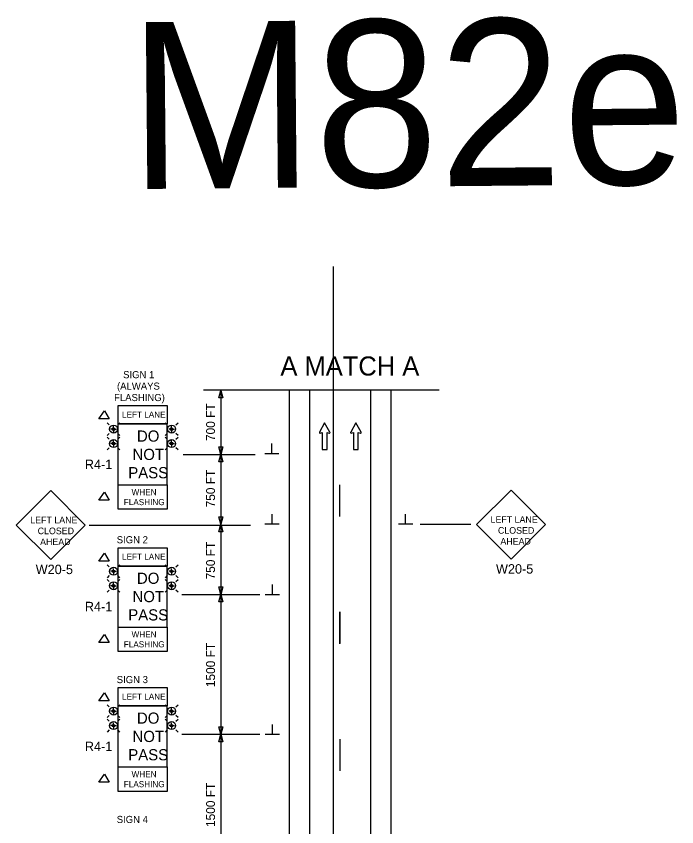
# Model space of a CAD drawing. Extents: x 15273 to 18137, y 1908 to 6555.
# Drawn here: x 16362 to 16881, y 2796 to 3433 of the extents above; entities that cross this region are included whole.
import ezdxf

# ---------------------------------------------------------------- set-up
doc = ezdxf.new("R2010")
doc.units = 0
for name, color, linetype in [('ALI_LEGAL_EX', 7, 'Continuous'), ('MT_SCRATCH_LEVEL_E', 7, 'Continuous'), ('PAVT_EDGE_EX', 7, 'Continuous'), ('TRAFFIC_SIGNS_PR', 7, 'Continuous'), ('TYPICAL_TEXT_DIMEN_PR', 7, 'Continuous')]:
    doc.layers.add(name, color=color, linetype=linetype)

msp = doc.modelspace()

# ---------------------------------------------------------------- linework, layer by layer
at = {"layer": 'ALI_LEGAL_EX'}
msp.add_line((16610.98, 3236.46), (16610.98, 2407.28), dxfattribs=at)
for points in [[(16616.07, 3064.67), (16616.07, 3039.67)], [(16616.07, 2964.67), (16616.07, 2939.67)], [(16616.35, 2964.74), (16616.35, 2939.74)], [(16616.35, 2864.74), (16616.35, 2839.74)]]:
    msp.add_lwpolyline(points, dxfattribs=at)
at = {"layer": 'MT_SCRATCH_LEVEL_E'}
for p, q in [((16604.32, 3113.3), (16600.21, 3106.06)), ((16608.47, 3106.06), (16604.32, 3113.3)), ((16628.88, 3113.3), (16624.77, 3106.06)), ((16633.03, 3106.06), (16628.88, 3113.3)), ((16600.69, 3105.38), (16602.47, 3105.69)), ((16602.47, 3105.69), (16602.47, 3092.43)), ((16606.21, 3092.43), (16606.21, 3105.69)), ((16606.21, 3105.69), (16607.99, 3105.38)), ((16625.25, 3105.38), (16627.03, 3105.69)), ((16627.03, 3105.69), (16627.03, 3092.43)), ((16630.77, 3092.43), (16630.77, 3105.69)), ((16630.77, 3105.69), (16632.55, 3105.38)), ((16602.47, 3092.43), (16606.21, 3092.43)), ((16627.03, 3092.43), (16630.77, 3092.43))]:
    msp.add_line(p, q, dxfattribs=at)
for centre, start, end in [((16600.62, 3105.84), 150.42484, 279.96381), ((16608.06, 3105.84), 260.03619, 29.77312), ((16625.17, 3105.84), 150.42484, 279.96381), ((16632.62, 3105.84), 260.03619, 29.77312)]:
    msp.add_arc(centre, 0.463, start, end, dxfattribs=at)
at = {"layer": 'PAVT_EDGE_EX'}
for p, q in [((16576.35, 3138.78), (16576.35, 2305.55)), ((16592.35, 3138.78), (16592.35, 2305.55)), ((16640.35, 3138.78), (16640.35, 2305.55)), ((16656.35, 3138.78), (16656.35, 2305.55))]:
    msp.add_line(p, q, dxfattribs=at)
at = {"layer": 'TRAFFIC_SIGNS_PR'}
for p, q in [((16434.9, 3111.91), (16433.27, 3113.53)), ((16441.74, 3111.91), (16443.37, 3113.53)), ((16442.06, 3064.61), (16442.06, 3112.61)), ((16442.06, 3112.61), (16480.46, 3112.61)), ((16480.54, 3111.92), (16478.91, 3113.55)), ((16480.46, 3064.61), (16480.46, 3112.61)), ((16487.39, 3111.92), (16489.02, 3113.55)), ((16434.9, 3105.06), (16433.27, 3103.43)), ((16438.32, 3108.48), (16436.02, 3108.48)), ((16438.32, 3108.48), (16438.32, 3110.78)), ((16438.32, 3108.48), (16438.32, 3105.33)), ((16438.32, 3108.48), (16440.62, 3108.48)), ((16443.37, 3103.43), (16441.74, 3105.06)), ((16480.54, 3105.07), (16478.91, 3103.45)), ((16483.96, 3108.5), (16481.66, 3108.5)), ((16483.96, 3108.5), (16483.96, 3110.8)), ((16483.96, 3108.5), (16483.96, 3105.35)), ((16483.96, 3108.5), (16486.27, 3108.5)), ((16489.01, 3103.45), (16487.39, 3105.07)), ((16434.9, 3100.53), (16433.27, 3102.16)), ((16438.32, 3097.11), (16438.32, 3099.41)), ((16441.74, 3100.53), (16443.37, 3102.16)), ((16480.54, 3100.53), (16478.91, 3102.16)), ((16483.96, 3097.11), (16483.96, 3099.41)), ((16487.39, 3100.53), (16489.02, 3102.16)), ((16434.9, 3093.68), (16433.27, 3092.06)), ((16438.32, 3097.11), (16436.02, 3097.11)), ((16438.32, 3097.11), (16438.32, 3093.96)), ((16438.32, 3097.11), (16440.62, 3097.11)), ((16443.37, 3092.06), (16441.74, 3093.68)), ((16480.54, 3093.68), (16478.91, 3092.06)), ((16483.96, 3097.11), (16481.66, 3097.11)), ((16483.96, 3097.11), (16483.96, 3093.96)), ((16483.96, 3097.11), (16486.27, 3097.11)), ((16489.01, 3092.06), (16487.39, 3093.68)), ((16388.92, 3060.19), (16361.77, 3033.04)), ((16416.08, 3033.04), (16388.92, 3060.19)), ((16442.06, 3064.61), (16480.46, 3064.61)), ((16750.87, 3060.57), (16723.72, 3033.42)), ((16778.03, 3033.42), (16750.87, 3060.57)), ((16361.77, 3033.04), (16388.92, 3005.88)), ((16388.92, 3005.88), (16416.08, 3033.04)), ((16723.72, 3033.42), (16750.87, 3006.26)), ((16750.87, 3006.26), (16778.03, 3033.42)), ((16434.9, 3000.08), (16433.27, 3001.71)), ((16438.32, 2996.66), (16436.02, 2996.66)), ((16438.32, 2996.66), (16438.32, 2998.96)), ((16438.32, 2996.66), (16438.32, 2993.51)), ((16438.32, 2996.66), (16440.62, 2996.66)), ((16441.74, 3000.08), (16443.37, 3001.71)), ((16442.06, 2952.78), (16442.06, 3000.78)), ((16442.06, 3000.78), (16480.46, 3000.78)), ((16480.54, 3000.1), (16478.91, 3001.72)), ((16480.46, 2952.78), (16480.46, 3000.78)), ((16483.96, 2996.67), (16481.66, 2996.67)), ((16483.96, 2996.67), (16483.96, 2998.97)), ((16483.96, 2996.67), (16483.96, 2993.52)), ((16483.96, 2996.67), (16486.27, 2996.67)), ((16487.39, 3000.1), (16489.02, 3001.72)), ((16434.9, 2993.23), (16433.27, 2991.6)), ((16434.9, 2988.71), (16433.27, 2990.33)), ((16443.37, 2991.6), (16441.74, 2993.23)), ((16441.74, 2988.7), (16443.37, 2990.33)), ((16480.54, 2993.25), (16478.91, 2991.62)), ((16480.54, 2988.71), (16478.91, 2990.33)), ((16489.01, 2991.62), (16487.39, 2993.25)), ((16487.39, 2988.7), (16489.02, 2990.33)), ((16438.32, 2985.28), (16436.02, 2985.28)), ((16438.32, 2985.28), (16438.32, 2987.58)), ((16438.32, 2985.28), (16438.32, 2982.13)), ((16438.32, 2985.28), (16440.62, 2985.28)), ((16483.96, 2985.28), (16481.66, 2985.28)), ((16483.96, 2985.28), (16483.96, 2987.58)), ((16483.96, 2985.28), (16483.96, 2982.13)), ((16483.96, 2985.28), (16486.27, 2985.28)), ((16434.9, 2981.86), (16433.27, 2980.23)), ((16443.37, 2980.23), (16441.74, 2981.86)), ((16480.54, 2981.86), (16478.91, 2980.23)), ((16489.01, 2980.23), (16487.39, 2981.86)), ((16442.06, 2952.78), (16480.46, 2952.78)), ((16434.9, 2890.08), (16433.27, 2891.71)), ((16438.32, 2886.66), (16438.32, 2888.96)), ((16441.74, 2890.08), (16443.37, 2891.71)), ((16442.06, 2842.78), (16442.06, 2890.78)), ((16442.06, 2890.78), (16480.46, 2890.78)), ((16480.54, 2890.1), (16478.91, 2891.72)), ((16480.46, 2842.78), (16480.46, 2890.78)), ((16483.96, 2886.67), (16483.96, 2888.97)), ((16487.39, 2890.1), (16489.02, 2891.72)), ((16434.9, 2883.23), (16433.27, 2881.6)), ((16438.32, 2886.66), (16436.02, 2886.66)), ((16438.32, 2886.66), (16438.32, 2883.51)), ((16438.32, 2886.66), (16440.62, 2886.66)), ((16443.37, 2881.6), (16441.74, 2883.23)), ((16480.54, 2883.25), (16478.91, 2881.62)), ((16483.96, 2886.67), (16481.66, 2886.67)), ((16483.96, 2886.67), (16483.96, 2883.52)), ((16483.96, 2886.67), (16486.27, 2886.67)), ((16489.01, 2881.62), (16487.39, 2883.25)), ((16434.9, 2878.71), (16433.27, 2880.33)), ((16438.32, 2875.28), (16436.02, 2875.28)), ((16438.32, 2875.28), (16438.32, 2877.58)), ((16438.32, 2875.28), (16438.32, 2872.13)), ((16438.32, 2875.28), (16440.62, 2875.28)), ((16441.74, 2878.7), (16443.37, 2880.33)), ((16480.54, 2878.71), (16478.91, 2880.33)), ((16483.96, 2875.28), (16481.66, 2875.28)), ((16483.96, 2875.28), (16483.96, 2877.58)), ((16483.96, 2875.28), (16483.96, 2872.13)), ((16483.96, 2875.28), (16486.27, 2875.28)), ((16487.39, 2878.7), (16489.02, 2880.33)), ((16434.9, 2871.86), (16433.27, 2870.23)), ((16443.37, 2870.23), (16441.74, 2871.86)), ((16480.54, 2871.86), (16478.91, 2870.23)), ((16489.01, 2870.23), (16487.39, 2871.86)), ((16442.06, 2842.78), (16480.46, 2842.78))]:
    msp.add_line(p, q, dxfattribs=at)
for centre, radius in [((16438.32, 3108.48), 3.15), ((16483.96, 3108.5), 3.15), ((16438.32, 3108.48), 1.02), ((16483.96, 3108.5), 1.02), ((16438.32, 3097.11), 3.15), ((16483.96, 3097.11), 3.15), ((16438.32, 3097.11), 1.02), ((16483.96, 3097.11), 1.02), ((16438.32, 2996.65), 3.15), ((16438.32, 2996.65), 1.02), ((16483.96, 2996.67), 3.15), ((16483.96, 2996.67), 1.02), ((16438.32, 2985.28), 3.15), ((16438.32, 2985.28), 1.02), ((16483.96, 2985.28), 3.15), ((16483.96, 2985.28), 1.02), ((16438.32, 2886.65), 3.15), ((16483.96, 2886.67), 3.15), ((16438.32, 2886.65), 1.02), ((16483.96, 2886.67), 1.02), ((16438.32, 2875.28), 3.15), ((16438.32, 2875.28), 1.02), ((16483.96, 2875.28), 3.15), ((16483.96, 2875.28), 1.02)]:
    msp.add_circle(centre, radius, dxfattribs=at)
at = {"layer": 'TYPICAL_TEXT_DIMEN_PR'}
for p, q in [((16508.93, 3139.37), (16694.24, 3139.37)), ((16521.05, 3133.07), (16522.62, 3138.93)), ((16522.62, 3138.93), (16524.19, 3133.07)), ((16522.62, 3138.65), (16522.62, 3068.65)), ((16522.62, 3133.07), (16521.05, 3133.07)), ((16524.19, 3133.07), (16522.62, 3133.07)), ((16522.62, 3088.64), (16521.05, 3094.51)), ((16521.05, 3094.51), (16522.62, 3094.51)), ((16522.62, 3094.51), (16524.19, 3094.51)), ((16524.19, 3094.51), (16522.62, 3088.64)), ((16562.78, 3089.31), (16562.78, 3097.09)), ((16492.95, 3088.64), (16549.74, 3088.64)), ((16521.05, 3082.78), (16522.62, 3088.64)), ((16522.62, 3088.64), (16522.62, 3018.64)), ((16522.62, 3088.64), (16524.19, 3082.78)), ((16557.15, 3089.31), (16568.4, 3089.31)), ((16522.62, 3082.78), (16521.05, 3082.78)), ((16524.19, 3082.78), (16522.62, 3082.78)), ((16563, 3033.88), (16563, 3041.66)), ((16667.92, 3033.77), (16667.92, 3041.56)), ((16522.62, 3033.66), (16521.06, 3039.53)), ((16521.06, 3039.53), (16522.62, 3039.53)), ((16522.62, 3039.53), (16524.19, 3039.53)), ((16524.19, 3039.53), (16522.62, 3033.66)), ((16419.26, 3032.92), (16546.13, 3032.92)), ((16521.05, 3027.82), (16522.62, 3033.68)), ((16522.62, 3033.68), (16524.19, 3027.82)), ((16522.62, 3033.48), (16522.62, 2963.48)), ((16557.38, 3033.88), (16568.62, 3033.88)), ((16673.55, 3033.77), (16662.3, 3033.77)), ((16719.39, 3033.52), (16679.35, 3033.52)), ((16522.62, 3027.82), (16521.05, 3027.82)), ((16524.19, 3027.82), (16522.62, 3027.82)), ((16522.62, 2978.48), (16521.06, 2984.34)), ((16521.06, 2984.34), (16522.62, 2984.34)), ((16522.62, 2988.35), (16522.62, 2984.58)), ((16522.62, 2984.34), (16524.19, 2984.34)), ((16524.19, 2984.34), (16522.62, 2978.48)), ((16563.23, 2978.48), (16563.23, 2986.26)), ((16491.89, 2978.48), (16553.35, 2978.48)), ((16521.06, 2972.61), (16522.62, 2978.48)), ((16522.62, 2978.48), (16522.62, 2868.48)), ((16522.62, 2978.48), (16524.19, 2972.61)), ((16557.6, 2978.48), (16568.85, 2978.48)), ((16522.62, 2972.61), (16521.06, 2972.61)), ((16524.19, 2972.61), (16522.62, 2972.61)), ((16563.23, 2868.48), (16563.23, 2876.26)), ((16522.62, 2868.48), (16521.06, 2874.34)), ((16521.06, 2874.34), (16522.62, 2874.34)), ((16522.62, 2874.34), (16524.19, 2874.34)), ((16524.19, 2874.34), (16522.62, 2868.48)), ((16491.89, 2868.48), (16553.35, 2868.48)), ((16521.06, 2862.61), (16522.62, 2868.48)), ((16522.62, 2862.61), (16521.06, 2862.61)), ((16522.62, 2868.48), (16522.62, 2758.48)), ((16522.62, 2868.48), (16524.19, 2862.61)), ((16524.19, 2862.61), (16522.62, 2862.61)), ((16557.6, 2868.48), (16568.85, 2868.48))]:
    msp.add_line(p, q, dxfattribs=at)
for points in [[(16442.06, 3127), (16480.46, 3127), (16480.46, 3112.61), (16442.06, 3112.61)], [(16426.76, 3116.5), (16431.12, 3122.8), (16434.83, 3116.5)], [(16442.06, 3064.61), (16480.46, 3064.61), (16480.46, 3045.41), (16442.06, 3045.41)], [(16426.76, 3052.53), (16431.12, 3058.83), (16434.83, 3052.53)], [(16426.76, 3004.67), (16431.12, 3010.97), (16434.83, 3004.67)], [(16442.06, 3015.18), (16480.46, 3015.18), (16480.46, 3000.78), (16442.06, 3000.78)], [(16442.06, 2952.78), (16480.46, 2952.78), (16480.46, 2933.59), (16442.06, 2933.59)], [(16426.76, 2940.7), (16431.12, 2947.01), (16434.83, 2940.7)], [(16426.76, 2894.67), (16431.12, 2900.97), (16434.83, 2894.67)], [(16442.06, 2905.18), (16480.46, 2905.18), (16480.46, 2890.78), (16442.06, 2890.78)], [(16426.76, 2830.7), (16431.12, 2837.01), (16434.83, 2830.7)], [(16442.06, 2842.78), (16480.46, 2842.78), (16480.46, 2823.59), (16442.06, 2823.59)]]:
    msp.add_lwpolyline(points, close=True, dxfattribs=at)

# ---------------------------------------------------------------- texts
at = {"layer": 'TRAFFIC_SIGNS_PR'}
for s, height, p in [('DO', 8.8, (16456.69, 3098.61)), ('NOT', 8.8, (16453.2, 3084.21)), ('R4-1', 7.44, (16415.74, 3077.03)), ('PASS', 8.8, (16449.85, 3069.81)), ('LEFT LANE', 5.2, (16372.8, 3034.43)), ('LEFT LANE', 5.2, (16734.75, 3034.81)), ('CLOSED', 5.2, (16378.64, 3025.83)), ('CLOSED', 5.2, (16740.59, 3026.21)), ('AHEAD', 5.2, (16380.58, 3017.23)), ('AHEAD', 5.2, (16742.53, 3017.61)), ('W20-5', 7.44, (16377.1, 2994.44)), ('W20-5', 7.44, (16739.05, 2994.82)), ('DO', 8.8, (16456.69, 2986.78)), ('NOT', 8.8, (16453.2, 2972.38)), ('R4-1', 7.44, (16415.74, 2965.2)), ('PASS', 8.8, (16449.85, 2957.98)), ('DO', 8.8, (16456.69, 2876.78)), ('NOT', 8.8, (16453.2, 2862.38)), ('R4-1', 7.44, (16415.74, 2855.2)), ('PASS', 8.8, (16449.85, 2847.98))]:
    msp.add_text(s, height=height, dxfattribs=at).set_placement(p)
at = {"layer": 'TYPICAL_TEXT_DIMEN_PR'}
for s, height, rotation, p in [('M82e', 131.22, 0.52295, (16450.52, 3297.22)), ('700 FT', 7, 90, (16518.1, 3099.09)), ('750 FT', 7, 90, (16518.1, 3046.9)), ('750 FT', 7, 90, (16518.1, 2990.25)), ('1500 FT', 7, 90, (16518.1, 2905.52)), ('1500 FT', 7, 90, (16518.1, 2795.52))]:
    msp.add_text(s, height=height, rotation=rotation, dxfattribs=at).set_placement(p)
for s, height, p in [('A MATCH A', 15, (16569.53, 3150.62)), (' SIGN 1 ', 5.6, (16443.76, 3148.51)), ('  (ALWAYS  ', 5.6, (16436.86, 3139.51)), ('  FLASHING) ', 5.6, (16434.55, 3130.51)), ('LEFT LANE', 4.8, (16444.98, 3117.51)), ('WHEN', 4.8, (16452.48, 3056.52)), ('FLASHING', 4.8, (16446.37, 3048.68)), ('   SIGN 2   ', 5.6, (16434.55, 3018.69)), ('LEFT LANE', 4.8, (16444.98, 3005.69)), ('WHEN', 4.8, (16452.48, 2944.69)), ('FLASHING', 4.8, (16446.37, 2936.86)), ('   SIGN 3   ', 5.6, (16434.56, 2908.69)), ('LEFT LANE', 4.8, (16444.98, 2895.69)), ('WHEN', 4.8, (16452.48, 2834.69)), ('FLASHING', 4.8, (16446.37, 2826.86)), ('   SIGN 4   ', 5.6, (16434.55, 2798.69))]:
    msp.add_text(s, height=height, dxfattribs=at).set_placement(p)

doc.saveas('drawing.dxf')
